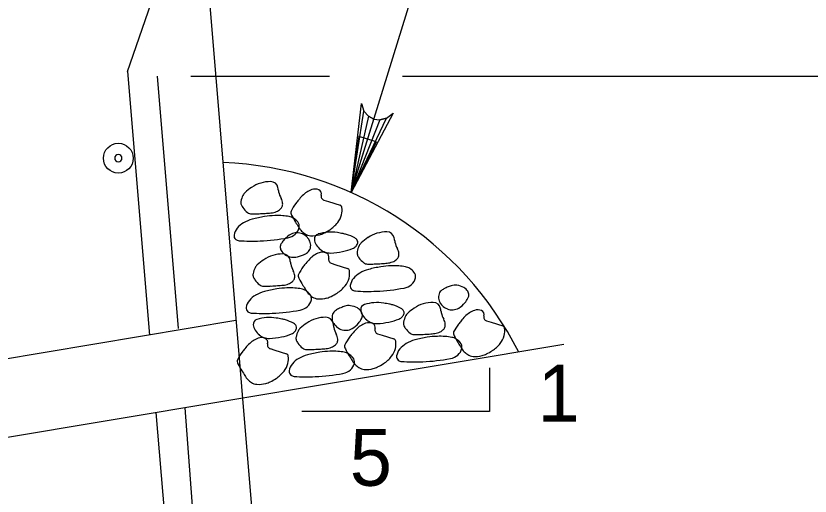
# Model space of a CAD drawing. Extents: x 638340 to 640241, y 295465 to 298435.
# Drawn here: x 639131.92 to 639173.9, y 296470.31 to 296495.68 of the extents above; entities that cross this region are included whole.
import ezdxf

# ---------------------------------------------------------------- set-up
doc = ezdxf.new("R2010")
doc.units = 0
for name, color, linetype in [('3', 7, 'Continuous'), ('4', 7, 'Continuous'), ('6', 7, 'Continuous'), ('8', 7, 'Continuous'), ('9', 7, 'Continuous')]:
    doc.layers.add(name, color=color, linetype=linetype)

# ---------------------------------------------------------------- blocks, each defined once
blk = doc.blocks.new('B')
at = {"layer": '3'}
blk.add_circle((0, 0), 0.1599, dxfattribs=at)
for start, end in [(0, 180), (180, 0)]:
    blk.add_arc((0, 0), 0.0391, start, end, dxfattribs=at)

msp = doc.modelspace()

# ---------------------------------------------------------------- linework, layer by layer
at = {"layer": '4'}
for p, q in [((639149.639, 296486.354), (639155.9, 296506.559)), ((639141.177, 296492.507), (639148.493, 296492.507)), ((639152.363, 296492.507), (639201.177, 296492.507))]:
    msp.add_line(p, q, dxfattribs=at)
for points in [[(639149.639, 296486.354), (639150.183, 296491.064), (639150.316, 296490.648), (639150.558, 296490.379), (639150.841, 296490.235), (639151.156, 296490.193), (639151.51, 296490.277), (639151.854, 296490.548), (639149.639, 296486.354), (639151.51, 296490.277), (639151.156, 296490.193), (639149.639, 296486.354), (639150.841, 296490.235), (639150.558, 296490.379), (639149.639, 296486.354), (639150.316, 296490.648)], [(639156.956, 296477.089), (639156.956, 296474.782), (639147.032, 296474.782)]]:
    msp.add_lwpolyline(points, dxfattribs=at)
msp.add_lwpolyline([(639150.983, 296489.029), (639150.041, 296489.316), (639149.651, 296486.347)], close=True, dxfattribs=at)
at = {"layer": '6'}
for p, q in [((639137.826, 296492.741), (639139.068, 296496.365)), ((639137.826, 296492.741), (639138.986, 296478.824)), ((639139.388, 296492.508), (639140.501, 296479.166)), ((639140.849, 296474.98), (639145.999, 296406.371)), ((639139.328, 296474.726), (639142.878, 296432.118))]:
    msp.add_line(p, q, dxfattribs=at)
at = {"layer": '8'}
for points in [[(639148.201, 296485.956), (639148.445, 296485.879), (639149.055, 296485.685)], [(639148.593, 296482.616), (639148.837, 296482.539), (639149.449, 296482.347)], [(639156.793, 296479.574), (639157.039, 296479.497), (639157.65, 296479.305)], [(639151.041, 296478.893), (639151.287, 296478.814), (639151.897, 296478.622)], [(639145.364, 296478.105), (639145.609, 296478.028), (639146.22, 296477.835)]]:
    msp.add_lwpolyline(points, dxfattribs=at)
for centre, radius, start, end in [((639146.031, 296484.188), 2.944, 124.1443, 132.7374), ((639145.376, 296485.154), 1.776, 89.5772, 124.1443), ((639145.386, 296486.535), 0.395, 11.4529, 89.5772), ((639144.451, 296486.346), 1.349, 6.1004, 11.4529), ((639147.735, 296486.035), 0.503, 65.9597, 109.6635), ((639145.073, 296485.631), 1.284, 153.538, 168.4897), ((639144.378, 296485.977), 0.507, 132.7374, 153.538), ((639146.695, 296486.586), 0.907, 186.1004, 192.6291), ((639147.111, 296486.679), 1.333, 192.6291, 208.6753), ((639151.081, 296482.359), 5.547, 136.4562, 139.6491), ((639148.002, 296485.286), 1.298, 109.6635, 136.4562), ((639147.845, 296486.283), 0.231, 342.3569, 65.9597), ((639148.261, 296486.151), 0.205, 162.3569, 252.4715), ((639144.12, 296485.825), 0.311, 168.4897, 199.1639), ((639144.349, 296485.905), 0.554, 199.1639, 207.4728), ((639145.33, 296485.705), 0.696, 6.391, 28.6753), ((639145.68, 296485.744), 0.344, 338.0834, 6.391), ((639149.521, 296483.752), 3.458, 144.1424, 152.1777), ((639148.989, 296484.137), 2.801, 139.6491, 144.1424), ((639144.642, 296486.058), 0.884, 207.4728, 214.0468), ((639144.784, 296486.154), 1.056, 214.0468, 234.0353), ((639144.38, 296485.596), 0.367, 234.0353, 268.2715), ((639144.23, 296498.171), 12.947, 273.846, 275.2114), ((639145.313, 296486.293), 1.019, 275.2114, 291.5731), ((639145.421, 296486.02), 0.726, 291.5731, 310.9894), ((639145.651, 296485.756), 0.375, 310.9894, 338.0834), ((639146.583, 296485.302), 0.136, 152.1777, 193.5774), ((639149.01, 296485.544), 0.148, 9.0416, 72.4715), ((639148.229, 296485.419), 0.939, 344.9373, 9.0416), ((639144.88, 296483.198), 1.809, 104.9239, 120.8473), ((639144.471, 296488.6), 3.372, 268.2715, 270.9097), ((639146.084, 296478.68), 6.485, 99.0416, 104.9239), ((639144.385, 296493.973), 8.746, 270.9097, 272.5478), ((639144.138, 296499.542), 14.321, 272.5478, 273.846), ((639145.736, 296480.87), 4.267, 91.7881, 99.0416), ((639145.734, 296480.934), 4.203, 86.0442, 91.7881), ((639145.83, 296482.322), 2.813, 79.021, 86.0442), ((639146.232, 296484.398), 0.698, 58.4341, 79.021), ((639146.92, 296485.384), 0.482, 193.5774, 207.4728), ((639152.251, 296488.156), 6.491, 207.4728, 211.2525), ((639146.116, 296484.208), 0.921, 40.5338, 58.4341), ((639148.028, 296485.473), 1.147, 321.7572, 344.9373), ((639144.158, 296484.007), 0.712, 139.2037, 172.3458), ((639144.652, 296483.58), 1.364, 120.8473, 139.2037), ((639146.303, 296484.613), 0.604, 309.5539, 349.0625), ((639161.531, 296493.787), 17.346, 211.2525, 212.2356), ((639146.537, 296484.568), 0.366, 349.0625, 40.5338), ((639150.054, 296486.55), 3.778, 212.2356, 214.3424), ((639147.55, 296485.85), 1.756, 303.0692, 321.7572), ((639143.697, 296484.068), 0.247, 172.3458, 230.2635), ((639147.065, 296483.001), 1.295, 117.4803, 136.4654), ((639146.131, 296484.821), 0.874, 280.7777, 309.5539), ((639146.786, 296483.537), 0.69, 91.376, 117.4803), ((639146.786, 296483.546), 0.681, 65.3457, 91.376), ((639147.41, 296484.743), 0.575, 214.3424, 227.6953), ((639148.217, 296485.63), 1.774, 227.6953, 235.2847), ((639146.744, 296483.456), 0.78, 41.057, 65.3457), ((639147.531, 296484.64), 0.569, 235.2847, 266.0442), ((639147.591, 296485.507), 1.438, 266.0442, 285.2565), ((639147.97, 296483.898), 0.275, 106.8084, 186.6218), ((639148.563, 296481.935), 2.327, 81.3134, 106.8084), ((639147.614, 296485.422), 1.351, 285.2565, 295.7443), ((639147, 296486.696), 2.765, 295.7443, 303.0692), ((639147.984, 296478.143), 6.162, 78.4814, 81.3134), ((639148.758, 296481.945), 2.282, 73.8272, 78.4814), ((639148.8, 296482.087), 2.134, 61.1605, 73.8272), ((639151.521, 296482.498), 1.776, 89.5772, 124.1443), ((639151.531, 296483.88), 0.395, 11.4529, 89.5772), ((639143.739, 296484.119), 0.312, 230.2635, 266.2346), ((639144.399, 296494.14), 10.356, 266.2346, 272.3841), ((639144.41, 296493.863), 10.078, 272.3841, 280.7777), ((639146.307, 296483.45), 0.414, 149.2422, 171.9761), ((639147.069, 296482.997), 1.3, 136.4654, 149.2422), ((639146.646, 296483.37), 0.91, 27.4728, 41.057), ((639147.057, 296483.584), 0.447, 8.0357, 27.4728), ((639146.93, 296483.566), 0.576, 337.0418, 8.0357), ((639148.278, 296483.934), 0.585, 186.6218, 200.3491), ((639148.396, 296483.978), 0.711, 200.3491, 212.797), ((639149.657, 296483.644), 0.357, 29.8544, 61.1605), ((639149.62, 296483.773), 0.376, 317.8475, 347.2445), ((639149.808, 296483.73), 0.183, 347.2445, 29.8544), ((639150.522, 296483.322), 0.507, 132.7374, 153.538), ((639152.176, 296481.532), 2.944, 124.1443, 132.7374), ((639150.596, 296483.69), 1.349, 6.1004, 11.4529), ((639152.839, 296483.93), 0.907, 186.1004, 192.6291), ((639153.255, 296484.023), 1.333, 192.6291, 208.6753), ((639146.234, 296483.46), 0.34, 171.9761, 209.5935), ((639146.46, 296483.589), 0.6, 209.5935, 237.6667), ((639147.088, 296483.499), 0.404, 299.831, 337.0418), ((639148.72, 296484.187), 1.097, 212.797, 230.2213), ((639148.127, 296482.696), 0.503, 65.9597, 109.6635), ((639148.535, 296483.964), 0.808, 230.2213, 250.5601), ((639148.533, 296483.959), 0.802, 250.5601, 271.915), ((639148.438, 296486.812), 3.657, 271.915, 281.8686), ((639148.548, 296486.286), 3.119, 281.8686, 292.039), ((639149.534, 296483.85), 0.491, 292.039, 317.8475), ((639150.264, 296483.17), 0.311, 168.4897, 199.1639), ((639151.217, 296482.975), 1.284, 153.538, 168.4897), ((639151.475, 296483.049), 0.696, 6.391, 28.6753), ((639146.675, 296480.366), 2.944, 124.1443, 132.7374), ((639146.019, 296481.332), 1.776, 89.5772, 124.1443), ((639146.03, 296482.714), 0.395, 11.4529, 89.5772), ((639146.687, 296483.947), 1.024, 237.6667, 259.0544), ((639145.094, 296482.525), 1.349, 6.1004, 11.4529), ((639146.618, 296483.591), 0.661, 259.0544, 285.7584), ((639145.491, 296487.584), 4.81, 285.7584, 288.5059), ((639146.617, 296484.22), 1.262, 288.5059, 293.8705), ((639146.669, 296484.103), 1.135, 293.8705, 297.4803), ((639145.958, 296485.47), 2.676, 297.4803, 299.831), ((639151.474, 296479.02), 5.547, 136.4562, 139.6491), ((639148.394, 296481.947), 1.298, 109.6635, 136.4562), ((639148.238, 296482.944), 0.231, 342.3569, 65.9597), ((639148.653, 296482.812), 0.205, 162.3569, 252.4715), ((639150.494, 296483.25), 0.554, 199.1639, 207.4728), ((639150.787, 296483.402), 0.884, 207.4728, 214.0468), ((639150.929, 296483.498), 1.056, 214.0468, 234.0353), ((639151.565, 296483.365), 0.726, 291.5731, 310.9894), ((639151.795, 296483.1), 0.375, 310.9894, 338.0834), ((639151.824, 296483.089), 0.344, 338.0834, 6.391), ((639145.716, 296481.81), 1.284, 153.538, 168.4897), ((639145.021, 296482.156), 0.507, 132.7374, 153.538), ((639147.338, 296482.764), 0.907, 186.1004, 192.6291), ((639147.754, 296482.857), 1.333, 192.6291, 208.6753), ((639149.913, 296480.413), 3.458, 144.1424, 152.1777), ((639149.382, 296480.798), 2.801, 139.6491, 144.1424), ((639149.402, 296482.205), 0.148, 9.0416, 72.4715), ((639150.524, 296482.941), 0.367, 234.0353, 268.2715), ((639150.615, 296485.944), 3.372, 268.2715, 270.9097), ((639152.229, 296476.024), 6.485, 99.0416, 104.9239), ((639150.53, 296491.317), 8.746, 270.9097, 272.5478), ((639150.282, 296496.887), 14.321, 272.5478, 273.846), ((639151.88, 296478.215), 4.267, 91.7881, 99.0416), ((639150.374, 296495.516), 12.947, 273.846, 275.2114), ((639151.457, 296483.638), 1.019, 275.2114, 291.5731), ((639151.878, 296478.279), 4.203, 86.0442, 91.7881), ((639151.974, 296479.666), 2.813, 79.021, 86.0442), ((639152.377, 296481.742), 0.698, 58.4341, 79.021), ((639144.763, 296482.004), 0.311, 168.4897, 199.1639), ((639145.974, 296481.884), 0.696, 6.391, 28.6753), ((639146.323, 296481.923), 0.344, 338.0834, 6.391), ((639146.976, 296481.964), 0.136, 152.1777, 193.5774), ((639147.313, 296482.045), 0.482, 193.5774, 207.4728), ((639148.622, 296482.08), 0.939, 344.9373, 9.0416), ((639150.796, 296480.925), 1.364, 120.8473, 139.2037), ((639151.024, 296480.543), 1.809, 104.9239, 120.8473), ((639152.26, 296481.552), 0.921, 40.5338, 58.4341), ((639152.681, 296481.912), 0.366, 349.0625, 40.5338), ((639144.992, 296482.084), 0.554, 199.1639, 207.4728), ((639145.285, 296482.236), 0.884, 207.4728, 214.0468), ((639145.428, 296482.332), 1.056, 214.0468, 234.0353), ((639145.956, 296482.472), 1.019, 275.2114, 291.5731), ((639146.064, 296482.199), 0.726, 291.5731, 310.9894), ((639146.294, 296481.935), 0.375, 310.9894, 338.0834), ((639152.644, 296484.817), 6.491, 207.4728, 211.2525), ((639148.421, 296482.135), 1.147, 321.7572, 344.9373), ((639150.302, 296481.351), 0.712, 139.2037, 172.3458), ((639152.448, 296481.958), 0.604, 309.5539, 349.0625), ((639145.523, 296479.377), 1.809, 104.9239, 120.8473), ((639145.023, 296481.775), 0.367, 234.0353, 268.2715), ((639145.114, 296484.778), 3.372, 268.2715, 270.9097), ((639146.727, 296474.858), 6.485, 99.0416, 104.9239), ((639145.029, 296490.152), 8.746, 270.9097, 272.5478), ((639144.781, 296495.721), 14.321, 272.5478, 273.846), ((639146.379, 296477.049), 4.267, 91.7881, 99.0416), ((639144.873, 296494.35), 12.947, 273.846, 275.2114), ((639146.377, 296477.113), 4.203, 86.0442, 91.7881), ((639146.473, 296478.5), 2.813, 79.021, 86.0442), ((639146.875, 296480.576), 0.698, 58.4341, 79.021), ((639161.923, 296490.448), 17.346, 211.2525, 212.2356), ((639146.759, 296480.386), 0.921, 40.5338, 58.4341), ((639150.447, 296483.211), 3.778, 212.2356, 214.3424), ((639147.802, 296481.404), 0.575, 214.3424, 227.6953), ((639147.942, 296482.512), 1.756, 303.0692, 321.7572), ((639149.842, 296481.413), 0.247, 172.3458, 230.2635), ((639149.884, 296481.463), 0.312, 230.2635, 266.2346), ((639150.543, 296491.485), 10.356, 266.2346, 272.3841), ((639150.555, 296491.208), 10.078, 272.3841, 280.7777), ((639152.276, 296482.166), 0.874, 280.7777, 309.5539), ((639154.67, 296480.866), 0.404, 122.9538, 160.1647), ((639155.906, 296478.959), 2.676, 120.6031, 122.9538), ((639155.121, 296480.286), 1.135, 116.9933, 120.6031), ((639155.179, 296480.172), 1.262, 111.6288, 116.9933), ((639156.487, 296476.874), 4.81, 108.8812, 111.6288), ((639155.144, 296480.8), 0.661, 82.1773, 108.8812), ((639155.095, 296480.44), 1.024, 60.7895, 82.1773), ((639155.302, 296480.81), 0.6, 32.7163, 60.7895), ((639155.521, 296480.951), 0.34, 355.0989, 32.7163), ((639145.295, 296479.759), 1.364, 120.8473, 139.2037), ((639146.946, 296480.792), 0.604, 309.5539, 349.0625), ((639148.609, 296482.291), 1.774, 227.6953, 235.2847), ((639147.18, 296480.747), 0.366, 349.0625, 40.5338), ((639147.923, 296481.301), 0.569, 235.2847, 266.0442), ((639147.983, 296482.168), 1.438, 266.0442, 285.2565), ((639148.006, 296482.083), 1.351, 285.2565, 295.7443), ((639147.392, 296483.357), 2.765, 295.7443, 303.0692), ((639154.832, 296480.808), 0.576, 160.1647, 191.1585), ((639154.705, 296480.783), 0.447, 191.1585, 210.5956), ((639154.662, 296481.368), 1.3, 319.5882, 332.365), ((639155.446, 296480.958), 0.414, 332.365, 355.0989), ((639144.34, 296480.247), 0.247, 172.3458, 230.2635), ((639144.801, 296480.185), 0.712, 139.2037, 172.3458), ((639146.775, 296481), 0.874, 280.7777, 309.5539), ((639149.554, 296479.092), 1.262, 111.6288, 116.9933), ((639150.861, 296475.794), 4.81, 108.8812, 111.6288), ((639149.519, 296479.72), 0.661, 82.1773, 108.8812), ((639149.469, 296479.36), 1.024, 60.7895, 82.1773), ((639149.676, 296479.73), 0.6, 32.7163, 60.7895), ((639150.419, 296480.173), 0.275, 106.8084, 186.6218), ((639151.012, 296478.209), 2.327, 81.3134, 106.8084), ((639150.433, 296474.418), 6.162, 78.4814, 81.3134), ((639151.207, 296478.22), 2.282, 73.8272, 78.4814), ((639151.248, 296478.362), 2.134, 61.1605, 73.8272), ((639154.625, 296477.807), 2.944, 124.1443, 132.7374), ((639153.969, 296478.773), 1.776, 89.5772, 124.1443), ((639153.98, 296480.155), 0.395, 11.4529, 89.5772), ((639155.104, 296481.018), 0.91, 210.5956, 224.1798), ((639155.011, 296480.928), 0.78, 224.1798, 248.4685), ((639154.974, 296480.845), 0.69, 274.4988, 300.6031), ((639154.666, 296481.365), 1.295, 300.6031, 319.5882), ((639144.382, 296480.298), 0.312, 230.2635, 266.2346), ((639145.042, 296490.319), 10.356, 266.2346, 272.3841), ((639145.053, 296490.042), 10.078, 272.3841, 280.7777), ((639149.206, 296479.727), 0.576, 160.1647, 191.1585), ((639149.044, 296479.786), 0.404, 122.9538, 160.1647), ((639150.28, 296477.879), 2.676, 120.6031, 122.9538), ((639149.496, 296479.205), 1.135, 116.9933, 120.6031), ((639150.727, 296480.209), 0.585, 186.6218, 200.3491), ((639150.845, 296480.253), 0.711, 200.3491, 212.797), ((639149.895, 296479.871), 0.34, 355.0989, 32.7163), ((639149.821, 296479.877), 0.414, 332.365, 355.0989), ((639151.169, 296480.462), 1.097, 212.797, 230.2213), ((639152.106, 296479.919), 0.357, 29.8544, 61.1605), ((639152.069, 296480.048), 0.376, 317.8475, 347.2445), ((639153.666, 296479.25), 1.284, 153.538, 168.4897), ((639152.256, 296480.005), 0.183, 347.2445, 29.8544), ((639152.971, 296479.597), 0.507, 132.7374, 153.538), ((639153.044, 296479.965), 1.349, 6.1004, 11.4529), ((639155.288, 296480.205), 0.907, 186.1004, 192.6291), ((639155.704, 296480.298), 1.333, 192.6291, 208.6753), ((639154.974, 296480.835), 0.681, 248.4685, 274.4988), ((639156.595, 296478.905), 1.298, 109.6635, 136.4562), ((639156.328, 296479.654), 0.503, 65.9597, 109.6635), ((639156.438, 296479.902), 0.231, 342.3569, 65.9597), ((639156.854, 296479.77), 0.205, 162.3569, 252.4715), ((639144.741, 296479.386), 0.275, 106.8084, 186.6218), ((639145.334, 296477.422), 2.327, 81.3134, 106.8084), ((639144.755, 296473.631), 6.162, 78.4814, 81.3134), ((639145.53, 296477.432), 2.282, 73.8272, 78.4814), ((639145.571, 296477.574), 2.134, 61.1605, 73.8272), ((639146.429, 296479.132), 0.357, 29.8544, 61.1605), ((639148.947, 296477.02), 2.944, 124.1443, 132.7374), ((639148.292, 296477.986), 1.776, 89.5772, 124.1443), ((639148.302, 296479.367), 0.395, 11.4529, 89.5772), ((639149.08, 296479.702), 0.447, 191.1585, 210.5956), ((639147.367, 296479.178), 1.349, 6.1004, 11.4529), ((639149.479, 296479.938), 0.91, 210.5956, 224.1798), ((639149.041, 296480.285), 1.295, 300.6031, 319.5882), ((639150.843, 296478.222), 1.298, 109.6635, 136.4562), ((639149.036, 296480.288), 1.3, 319.5882, 332.365), ((639150.576, 296478.971), 0.503, 65.9597, 109.6635), ((639150.984, 296480.239), 0.808, 230.2213, 250.5601), ((639150.982, 296480.234), 0.802, 250.5601, 271.915), ((639150.686, 296479.219), 0.231, 342.3569, 65.9597), ((639150.886, 296483.087), 3.657, 271.915, 281.8686), ((639150.997, 296482.561), 3.119, 281.8686, 292.039), ((639151.983, 296480.125), 0.491, 292.039, 317.8475), ((639152.713, 296479.445), 0.311, 168.4897, 199.1639), ((639153.924, 296479.324), 0.696, 6.391, 28.6753), ((639154.273, 296479.364), 0.344, 338.0834, 6.391), ((639157.582, 296477.756), 2.801, 139.6491, 144.1424), ((639159.675, 296475.978), 5.547, 136.4562, 139.6491), ((639145.049, 296479.422), 0.585, 186.6218, 200.3491), ((639145.167, 296479.466), 0.711, 200.3491, 212.797), ((639145.492, 296479.675), 1.097, 212.797, 230.2213), ((639146.306, 296479.338), 0.491, 292.039, 317.8475), ((639146.391, 296479.26), 0.376, 317.8475, 347.2445), ((639147.989, 296478.463), 1.284, 153.538, 168.4897), ((639146.579, 296479.218), 0.183, 347.2445, 29.8544), ((639147.294, 296478.809), 0.507, 132.7374, 153.538), ((639149.61, 296479.417), 0.907, 186.1004, 192.6291), ((639150.026, 296479.511), 1.333, 192.6291, 208.6753), ((639149.385, 296479.848), 0.78, 224.1798, 248.4685), ((639149.349, 296479.755), 0.681, 248.4685, 274.4988), ((639149.348, 296479.765), 0.69, 274.4988, 300.6031), ((639153.923, 296475.295), 5.547, 136.4562, 139.6491), ((639151.102, 296479.087), 0.205, 162.3569, 252.4715), ((639152.942, 296479.524), 0.554, 199.1639, 207.4728), ((639153.235, 296479.677), 0.884, 207.4728, 214.0468), ((639153.378, 296479.773), 1.056, 214.0468, 234.0353), ((639154.014, 296479.64), 0.726, 291.5731, 310.9894), ((639154.244, 296479.375), 0.375, 310.9894, 338.0834), ((639155.177, 296478.922), 0.136, 152.1777, 193.5774), ((639158.114, 296477.371), 3.458, 144.1424, 152.1777), ((639157.603, 296479.163), 0.148, 9.0416, 72.4715), ((639156.822, 296479.039), 0.939, 344.9373, 9.0416), ((639145.166, 296477.434), 1.298, 109.6635, 136.4562), ((639144.898, 296478.183), 0.503, 65.9597, 109.6635), ((639145.306, 296479.452), 0.808, 230.2213, 250.5601), ((639145.304, 296479.446), 0.802, 250.5601, 271.915), ((639145.009, 296478.432), 0.231, 342.3569, 65.9597), ((639145.209, 296482.3), 3.657, 271.915, 281.8686), ((639145.32, 296481.773), 3.119, 281.8686, 292.039), ((639147.035, 296478.657), 0.311, 168.4897, 199.1639), ((639148.246, 296478.537), 0.696, 6.391, 28.6753), ((639148.595, 296478.576), 0.344, 338.0834, 6.391), ((639152.362, 296476.688), 3.458, 144.1424, 152.1777), ((639151.83, 296477.073), 2.801, 139.6491, 144.1424), ((639151.851, 296478.48), 0.148, 9.0416, 72.4715), ((639153.473, 296476.818), 1.809, 104.9239, 120.8473), ((639152.973, 296479.215), 0.367, 234.0353, 268.2715), ((639153.064, 296482.219), 3.372, 268.2715, 270.9097), ((639154.677, 296472.299), 6.485, 99.0416, 104.9239), ((639152.978, 296487.592), 8.746, 270.9097, 272.5478), ((639152.731, 296493.162), 14.321, 272.5478, 273.846), ((639154.329, 296474.49), 4.267, 91.7881, 99.0416), ((639152.823, 296491.791), 12.947, 273.846, 275.2114), ((639153.906, 296479.912), 1.019, 275.2114, 291.5731), ((639154.327, 296474.554), 4.203, 86.0442, 91.7881), ((639154.423, 296475.941), 2.813, 79.021, 86.0442), ((639154.825, 296478.017), 0.698, 58.4341, 79.021), ((639155.514, 296479.003), 0.482, 193.5774, 207.4728), ((639160.845, 296481.775), 6.491, 207.4728, 211.2525), ((639154.709, 296477.827), 0.921, 40.5338, 58.4341), ((639156.622, 296479.093), 1.147, 321.7572, 344.9373), ((639148.245, 296474.508), 5.547, 136.4562, 139.6491), ((639145.425, 296478.299), 0.205, 162.3569, 252.4715), ((639147.265, 296478.737), 0.554, 199.1639, 207.4728), ((639147.558, 296478.889), 0.884, 207.4728, 214.0468), ((639147.7, 296478.986), 1.056, 214.0468, 234.0353), ((639148.229, 296479.125), 1.019, 275.2114, 291.5731), ((639148.337, 296478.852), 0.726, 291.5731, 310.9894), ((639148.567, 296478.588), 0.375, 310.9894, 338.0834), ((639149.425, 296478.239), 0.136, 152.1777, 193.5774), ((639149.762, 296478.32), 0.482, 193.5774, 207.4728), ((639151.07, 296478.355), 0.939, 344.9373, 9.0416), ((639153.245, 296477.2), 1.364, 120.8473, 139.2037), ((639170.124, 296487.407), 17.346, 211.2525, 212.2356), ((639155.13, 296478.187), 0.366, 349.0625, 40.5338), ((639158.648, 296480.169), 3.778, 212.2356, 214.3424), ((639156.143, 296479.47), 1.756, 303.0692, 321.7572), ((639146.685, 296475.901), 3.458, 144.1424, 152.1777), ((639146.153, 296476.285), 2.801, 139.6491, 144.1424), ((639146.174, 296477.692), 0.148, 9.0416, 72.4715), ((639147.796, 296476.03), 1.809, 104.9239, 120.8473), ((639147.296, 296478.428), 0.367, 234.0353, 268.2715), ((639147.386, 296481.432), 3.372, 268.2715, 270.9097), ((639149, 296471.512), 6.485, 99.0416, 104.9239), ((639147.301, 296486.805), 8.746, 270.9097, 272.5478), ((639147.053, 296492.374), 14.321, 272.5478, 273.846), ((639148.651, 296473.702), 4.267, 91.7881, 99.0416), ((639147.145, 296491.003), 12.947, 273.846, 275.2114), ((639148.649, 296473.766), 4.203, 86.0442, 91.7881), ((639148.745, 296475.154), 2.813, 79.021, 86.0442), ((639149.148, 296477.23), 0.698, 58.4341, 79.021), ((639155.093, 296481.092), 6.491, 207.4728, 211.2525), ((639149.031, 296477.04), 0.921, 40.5338, 58.4341), ((639164.372, 296486.723), 17.346, 211.2525, 212.2356), ((639150.87, 296478.409), 1.147, 321.7572, 344.9373), ((639152.751, 296477.626), 0.712, 139.2037, 172.3458), ((639154.725, 296478.441), 0.874, 280.7777, 309.5539), ((639154.896, 296478.233), 0.604, 309.5539, 349.0625), ((639156.003, 296478.362), 0.575, 214.3424, 227.6953), ((639156.81, 296479.249), 1.774, 227.6953, 235.2847), ((639156.124, 296478.259), 0.569, 235.2847, 266.0442), ((639156.184, 296479.126), 1.438, 266.0442, 285.2565), ((639156.207, 296479.041), 1.351, 285.2565, 295.7443), ((639155.593, 296480.315), 2.765, 295.7443, 303.0692), ((639143.747, 296477.451), 0.136, 152.1777, 193.5774), ((639144.084, 296477.533), 0.482, 193.5774, 207.4728), ((639149.415, 296480.305), 6.491, 207.4728, 211.2525), ((639145.192, 296477.622), 1.147, 321.7572, 344.9373), ((639145.393, 296477.568), 0.939, 344.9373, 9.0416), ((639147.074, 296476.838), 0.712, 139.2037, 172.3458), ((639147.568, 296476.412), 1.364, 120.8473, 139.2037), ((639149.219, 296477.445), 0.604, 309.5539, 349.0625), ((639152.896, 296479.486), 3.778, 212.2356, 214.3424), ((639149.453, 296477.4), 0.366, 349.0625, 40.5338), ((639150.251, 296477.679), 0.575, 214.3424, 227.6953), ((639149.841, 296479.632), 2.765, 295.7443, 303.0692), ((639150.391, 296478.786), 1.756, 303.0692, 321.7572), ((639152.29, 296477.688), 0.247, 172.3458, 230.2635), ((639152.332, 296477.738), 0.312, 230.2635, 266.2346), ((639152.992, 296487.76), 10.356, 266.2346, 272.3841), ((639153.003, 296487.483), 10.078, 272.3841, 280.7777), ((639158.695, 296485.936), 17.346, 211.2525, 212.2356), ((639144.714, 296477.999), 1.756, 303.0692, 321.7572), ((639146.613, 296476.9), 0.247, 172.3458, 230.2635), ((639149.047, 296477.653), 0.874, 280.7777, 309.5539), ((639151.058, 296478.566), 1.774, 227.6953, 235.2847), ((639150.372, 296477.576), 0.569, 235.2847, 266.0442), ((639150.432, 296478.443), 1.438, 266.0442, 285.2565), ((639150.455, 296478.358), 1.351, 285.2565, 295.7443), ((639147.218, 296478.699), 3.778, 212.2356, 214.3424), ((639144.573, 296476.892), 0.575, 214.3424, 227.6953), ((639145.38, 296477.779), 1.774, 227.6953, 235.2847), ((639144.163, 296478.845), 2.765, 295.7443, 303.0692), ((639146.655, 296476.951), 0.312, 230.2635, 266.2346), ((639147.315, 296486.972), 10.356, 266.2346, 272.3841), ((639147.326, 296486.695), 10.078, 272.3841, 280.7777), ((639144.695, 296476.789), 0.569, 235.2847, 266.0442), ((639144.754, 296477.656), 1.438, 266.0442, 285.2565), ((639144.778, 296477.571), 1.351, 285.2565, 295.7443)]:
    msp.add_arc(centre, radius, start, end, dxfattribs=at)
at = {"layer": '9'}
for p, q in [((639136.282, 296566.837), (639147.637, 296430.58)), ((639143.553, 296479.587), (639117.762, 296475.289)), ((639160.879, 296478.318), (639117.762, 296471.132))]:
    msp.add_line(p, q, dxfattribs=at)
msp.add_arc((639142.155, 296469.617), 18.332, 26.9324, 87.7453, dxfattribs=at)

# ---------------------------------------------------------------- block references
at = {"layer": '3', "xscale": 4.921475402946, "yscale": 4.921475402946, "rotation": 90}
msp.add_blockref('B', (639137.338, 296488.166), dxfattribs=at)

# ---------------------------------------------------------------- texts
at = {"layer": '4'}
for s, p in [('1', (639159.491, 296474.251)), ('5', (639149.568, 296470.861))]:
    msp.add_text(s, height=3, dxfattribs=at).set_placement(p)

doc.saveas('drawing.dxf')
